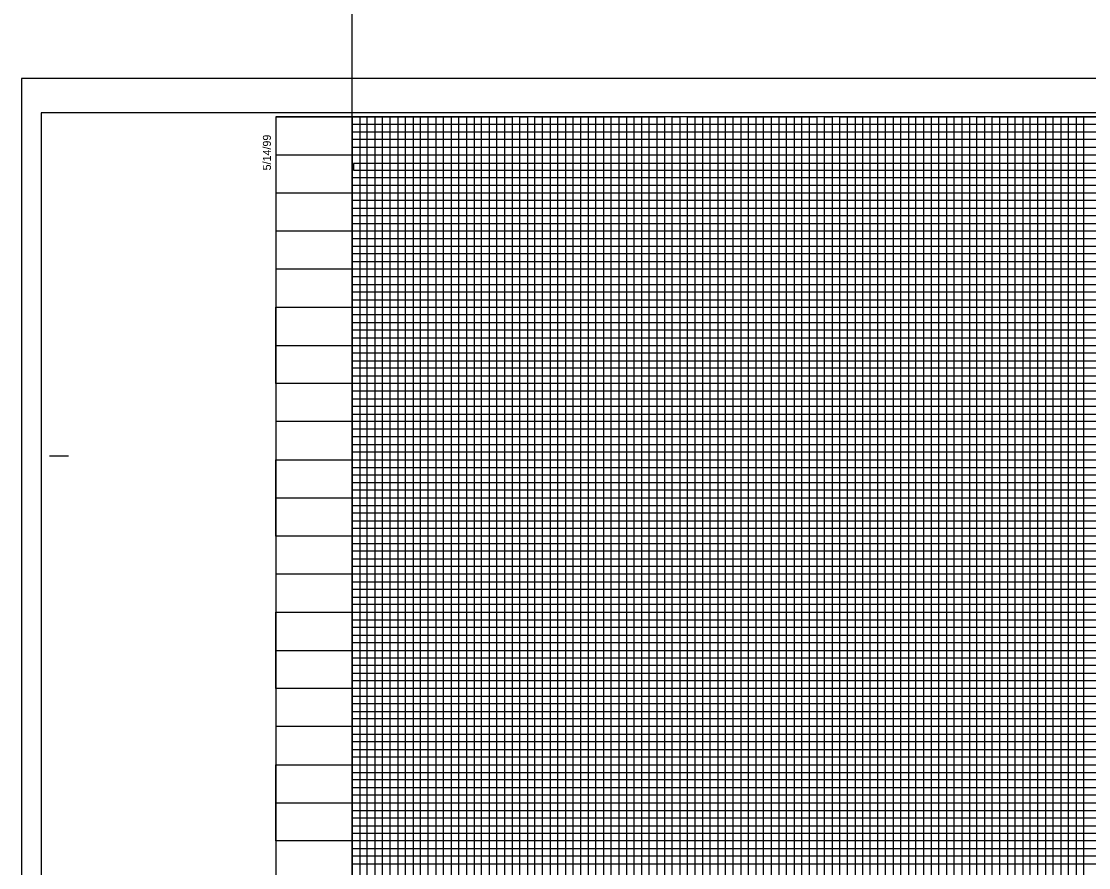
# Model space of a CAD drawing. Extents: x 2345490 to 2436403, y 465165 to 573888.
# Drawn here: x 2381550 to 2382250, y 541557 to 542112 of the extents above; entities that cross this region are included whole.
import ezdxf

# ---------------------------------------------------------------- set-up
doc = ezdxf.new("R2010")
doc.units = 0
for name, color, linetype in [('Old_Level_18', 7, 'Continuous'), ('Old_Level_41', 7, 'Continuous'), ('Old_Level_42', 7, 'Continuous'), ('Old_Level_43', 7, 'Continuous'), ('Old_Level_50', 7, 'Continuous'), ('Old_Level_51', 7, 'Continuous'), ('Old_Level_63', 7, 'Continuous')]:
    doc.layers.add(name, color=color, linetype=linetype)

msp = doc.modelspace()

# ---------------------------------------------------------------- linework, layer by layer
at = {"layer": 'Old_Level_18'}
msp.add_lwpolyline([(2383216.79875, 542049.5045), (2381716.79875, 542049.5045), (2381716.79875, 540999.5045), (2383216.79875, 540999.5045)], close=True, dxfattribs=at)
at = {"layer": 'Old_Level_41'}
msp.add_line((2381568.29875, 541827.0045), (2381580.79875, 541827.0045), dxfattribs=at)
for points in [[(2381716.79875, 542049.5045), (2381766.79875, 542049.5045), (2381766.79875, 541024.5045), (2381816.79875, 541024.5045), (2381816.79875, 542049.5045), (2381866.79875, 542049.5045), (2381866.79875, 541024.5045), (2381916.79875, 541024.5045), (2381916.79875, 542049.5045), (2381966.79875, 542049.5045), (2381966.79875, 541024.5045), (2382016.79875, 541024.5045), (2382016.79875, 542049.5045), (2382066.79875, 542049.5045), (2382066.79875, 541024.5045), (2382116.79875, 541024.5045), (2382116.79875, 542049.5045), (2382166.79875, 542049.5045), (2382166.79875, 541024.5045), (2382216.79875, 541024.5045), (2382216.79875, 542049.5045), (2382266.79875, 542049.5045)], [(2381791.79875, 541024.5045), (2381791.79875, 542049.5045), (2381841.79875, 542049.5045), (2381841.79875, 541024.5045), (2381891.79875, 541024.5045), (2381891.79875, 542049.5045), (2381941.79875, 542049.5045), (2381941.79875, 541024.5045), (2381991.79875, 541024.5045), (2381991.79875, 542049.5045), (2382041.79875, 542049.5045), (2382041.79875, 541024.5045), (2382091.79875, 541024.5045), (2382091.79875, 542049.5045), (2382141.79875, 542049.5045), (2382141.79875, 541024.5045), (2382191.79875, 541024.5045), (2382191.79875, 542049.5045), (2382241.79875, 542049.5045), (2382241.79875, 541024.5045), (2382291.79875, 541024.5045)], [(2381716.79875, 541999.5045), (2383016.74875, 541999.5045)], [(2383016.74875, 541949.5045), (2381716.79875, 541949.5045), (2381716.79875, 541899.4545), (2383216.79875, 541899.4545)], [(2383216.79875, 541874.5045), (2381716.79875, 541874.5045), (2381716.79875, 541924.5045), (2383016.74875, 541924.5045)], [(2383216.79875, 541849.5045), (2381716.79875, 541849.5045), (2381716.79875, 541799.5045), (2383216.79875, 541799.5045)], [(2383216.79875, 541774.5045), (2381716.79875, 541774.5045), (2381716.79875, 541824.5045), (2383216.79875, 541824.5045)], [(2383216.79875, 541749.5045), (2381716.79875, 541749.5045), (2381716.79875, 541699.5045), (2383216.79875, 541699.5045)], [(2383216.79875, 541649.5045), (2381716.79875, 541649.5045), (2381716.79875, 541599.5045), (2383216.79875, 541599.5045)]]:
    msp.add_lwpolyline(points, dxfattribs=at)
at = {"layer": 'Old_Level_42'}
for points in [[(2383016.74875, 541974.5045), (2381716.89875, 541974.5045), (2381716.89875, 542024.4545), (2383016.74875, 542024.4545)], [(2383216.79875, 541674.5045), (2381716.79875, 541674.5045), (2381716.79875, 541724.5045), (2383216.79875, 541724.5045)], [(2383216.79875, 541574.5045), (2381716.79875, 541574.5045), (2381716.79875, 541624.5045), (2383216.79875, 541624.5045)]]:
    msp.add_lwpolyline(points, dxfattribs=at)
at = {"layer": 'Old_Level_43'}
for p, q in [((2383166.79875, 541869.5045), (2381766.79875, 541869.5045)), ((2381766.79875, 541869.5045), (2381766.79875, 541864.5045)), ((2381766.79875, 541864.5045), (2383166.79875, 541864.5045)), ((2383166.79875, 541844.5045), (2381766.79875, 541844.5045))]:
    msp.add_line(p, q, dxfattribs=at)
for points in [[(2381771.79875, 542049.5045), (2381776.79875, 542049.5045), (2381781.79875, 542049.5045), (2381786.79875, 542049.5045), (2381796.79875, 542049.5045), (2381763.74875, 542049.5045), (2381768.74875, 542049.5045), (2381726.79875, 542049.5045), (2381731.79875, 542049.5045), (2381736.79875, 542049.5045), (2381746.79875, 542049.5045), (2381751.79875, 542049.5045), (2381756.79875, 542049.5045), (2381761.79875, 542049.5045), (2381771.79875, 542049.5045), (2381771.79875, 541024.5045)], [(2381776.79875, 541024.5045), (2381776.79875, 542049.5045), (2381781.79875, 542049.5045), (2381781.79875, 541024.5045)], [(2381786.79875, 541024.5045), (2381786.79875, 542049.5045), (2381796.79875, 542049.5045), (2381796.79875, 541024.5045)], [(2381801.79875, 541024.5045), (2381801.79875, 542049.5045), (2381806.79875, 542049.5045), (2381806.79875, 541024.5045)], [(2381811.79875, 541024.5045), (2381811.79875, 542049.5045), (2381821.79875, 542049.5045), (2381821.79875, 541024.5045)], [(2381826.79875, 541024.5045), (2381826.79875, 542049.5045), (2381831.79875, 542049.5045), (2381831.79875, 541024.5045)], [(2381836.79875, 541024.5045), (2381836.79875, 542049.5045), (2381846.79875, 542049.5045), (2381846.79875, 541024.5045)], [(2381851.79875, 541024.5045), (2381851.79875, 542049.5045), (2381856.79875, 542049.5045), (2381856.79875, 541024.5045)], [(2381861.79875, 541024.5045), (2381861.79875, 542049.5045), (2381871.79875, 542049.5045), (2381871.79875, 541024.5045)], [(2381876.79875, 541024.5045), (2381876.79875, 542049.5045), (2381881.79875, 542049.5045), (2381881.79875, 541024.5045)], [(2381886.79875, 541024.5045), (2381886.79875, 542049.5045), (2381896.79875, 542049.5045), (2381896.79875, 541024.5045)], [(2381901.79875, 541024.5045), (2381901.79875, 542049.5045), (2381906.79875, 542049.5045), (2381906.79875, 541024.5045)], [(2381911.79875, 541024.5045), (2381911.79875, 542049.5045), (2381921.79875, 542049.5045), (2381921.79875, 541024.5045)], [(2381926.79875, 541024.5045), (2381926.79875, 542049.5045), (2381931.79875, 542049.5045), (2381931.79875, 541024.5045)], [(2381936.79875, 541024.5045), (2381936.79875, 542049.5045), (2381946.79875, 542049.5045), (2381946.79875, 541024.5045)], [(2381951.79875, 541024.5045), (2381951.79875, 542049.5045), (2381956.79875, 542049.5045), (2381956.79875, 541024.5045)], [(2381961.79875, 541024.5045), (2381961.79875, 542049.5045), (2381971.79875, 542049.5045), (2381971.79875, 541024.5045)], [(2381976.79875, 541024.5045), (2381976.79875, 542049.5045), (2381976.79875, 542049.5045), (2381981.79875, 542049.5045), (2381981.79875, 541024.5045)], [(2381986.79875, 541024.5045), (2381986.79875, 542049.5045), (2381996.79875, 542049.5045), (2381996.79875, 541024.5045)], [(2382001.79875, 541024.5045), (2382001.79875, 542049.5045), (2382006.79875, 542049.5045), (2382006.79875, 541024.5045)], [(2382011.79875, 541024.5045), (2382011.79875, 542049.5045), (2382021.79875, 542049.5045), (2382021.79875, 541024.5045)], [(2382026.79875, 541024.5045), (2382026.79875, 542049.5045), (2382031.79875, 542049.5045), (2382031.79875, 541024.5045)], [(2382036.79875, 541024.5045), (2382036.79875, 542049.5045), (2382046.79875, 542049.5045), (2382046.79875, 541024.5045)], [(2382051.79875, 541024.5045), (2382051.79875, 542049.5045), (2382056.79875, 542049.5045), (2382056.79875, 541024.5045)], [(2382061.79875, 541024.5045), (2382061.79875, 542049.5045), (2382071.79875, 542049.5045), (2382071.79875, 541024.5045)], [(2382076.79875, 541024.5045), (2382076.79875, 542049.5045), (2382081.79875, 542049.5045), (2382081.79875, 541024.5045)], [(2382086.79875, 541024.5045), (2382086.79875, 542049.5045), (2382096.79875, 542049.5045), (2382096.79875, 541024.5045)], [(2382101.79875, 542049.5045), (2382101.79875, 541024.5045), (2382106.79875, 541024.5045), (2382106.79875, 542049.5045)], [(2382101.79875, 542048.9045), (2382101.79875, 541024.5045), (2382106.79875, 541024.5045), (2382106.79875, 542048.9045)], [(2382111.79875, 541024.5045), (2382111.79875, 542049.5045), (2382121.79875, 542049.5045), (2382121.79875, 541024.5045)], [(2382126.79875, 541024.5045), (2382126.79875, 542049.5045), (2382131.79875, 542049.5045), (2382131.79875, 541024.5045)], [(2382136.79875, 541024.5045), (2382136.79875, 542049.5045), (2382146.79875, 542049.5045), (2382146.79875, 541024.5045)], [(2382151.79875, 541024.5045), (2382151.79875, 542049.5045), (2382156.79875, 542049.5045), (2382156.79875, 541024.5045)], [(2382161.79875, 541024.5045), (2382161.79875, 542049.5045), (2382171.79875, 542049.5045), (2382171.79875, 541024.5045)], [(2382176.79875, 541024.5045), (2382176.79875, 542049.5045), (2382181.79875, 542049.5045), (2382181.79875, 541024.5045)], [(2382186.79875, 541024.5045), (2382186.79875, 542049.5045), (2382196.79875, 542049.5045), (2382196.79875, 541024.5045)], [(2382201.79875, 541024.5045), (2382201.79875, 542049.5045), (2382206.79875, 542049.5045), (2382206.79875, 541024.5045)], [(2382211.79875, 541024.5045), (2382211.79875, 542049.5045), (2382221.79875, 542049.5045), (2382221.79875, 541024.5045)], [(2382226.79875, 541024.5045), (2382226.79875, 542049.5045), (2382231.79875, 542049.5045), (2382231.79875, 541024.5045)], [(2382236.79875, 541024.5045), (2382236.79875, 542049.5045), (2382246.79875, 542049.5045), (2382246.79875, 541024.5045)], [(2383016.74875, 542044.5045), (2381766.79875, 542044.5045), (2381766.79875, 542039.5045), (2383016.74875, 542039.5045)], [(2383016.74875, 542034.5045), (2381766.79875, 542034.5045), (2381766.79875, 542029.5045), (2383016.74875, 542029.5045)], [(2383016.74875, 542018.7545), (2381767.79875, 542018.7545), (2381767.79875, 542014.5045), (2383016.74875, 542014.5045)], [(2383016.74875, 542009.5045), (2381766.79875, 542009.5045), (2381766.79875, 542004.5045), (2383016.74875, 542004.5045)], [(2383016.74875, 541994.5045), (2381766.79875, 541994.5045), (2381766.79875, 541989.5045), (2383016.74875, 541989.5045)], [(2383016.74875, 541984.5045), (2381766.79875, 541984.5045), (2381766.79875, 541979.5045), (2383016.74875, 541979.5045)], [(2383016.74875, 541969.5045), (2381766.79875, 541969.5045), (2381766.79875, 541964.5045), (2383016.74875, 541964.5045)], [(2383016.74875, 541959.5045), (2381766.79875, 541959.5045), (2381766.79875, 541954.5045), (2383016.74875, 541954.5045)], [(2383016.74875, 541944.5045), (2381766.79875, 541944.5045), (2381766.79875, 541939.5045), (2383016.74875, 541939.5045)], [(2383016.74875, 541934.5045), (2381766.79875, 541934.5045), (2381766.79875, 541929.5045), (2383016.74875, 541929.5045)], [(2383016.74875, 541919.5045), (2381766.79875, 541919.5045), (2381766.79875, 541914.5045), (2383016.74875, 541914.5045)], [(2383166.79875, 541909.5045), (2381766.79875, 541909.5045), (2381766.79875, 541909.5045), (2381766.79875, 541889.5045), (2383166.79875, 541889.5045)], [(2381766.79875, 541904.5045), (2383166.79875, 541904.5045)], [(2383166.79875, 541894.5045), (2381766.79875, 541894.5045)], [(2383166.79875, 541884.5045), (2381766.79875, 541884.5045), (2381766.79875, 541879.5045), (2383166.79875, 541879.5045)], [(2383166.79875, 541859.5045), (2381766.79875, 541859.5045), (2381766.79875, 541854.5045), (2383166.79875, 541854.5045)], [(2383166.79875, 541839.5045), (2381766.79875, 541839.5045), (2381766.79875, 541834.5045), (2383166.79875, 541834.5045)], [(2383166.79875, 541829.5045), (2381766.79875, 541829.5045)], [(2381766.79875, 541819.5045), (2383166.79875, 541819.5045)], [(2383166.79875, 541814.5045), (2381766.79875, 541814.5045), (2381766.79875, 541809.5045), (2383166.79875, 541809.5045)], [(2383166.79875, 541804.5045), (2381766.79875, 541804.5045), (2381766.79875, 541794.5045), (2383166.79875, 541794.5045)], [(2383166.79875, 541789.5045), (2381766.79875, 541789.5045), (2381766.79875, 541784.5045), (2383166.79875, 541784.5045)], [(2383166.79875, 541779.5045), (2381766.79875, 541779.5045), (2381766.79875, 541769.5045), (2383166.79875, 541769.5045)], [(2383166.79875, 541764.5045), (2381766.79875, 541764.5045), (2381766.79875, 541759.5045), (2383166.79875, 541759.5045)], [(2383166.79875, 541754.5045), (2381766.79875, 541754.5045), (2381766.79875, 541744.5045), (2383166.79875, 541744.5045)], [(2383166.79875, 541739.5045), (2381766.79875, 541739.5045), (2381766.79875, 541734.5045), (2383166.79875, 541734.5045)], [(2383166.79875, 541729.5045), (2381766.79875, 541729.5045), (2381766.79875, 541719.5045), (2383166.79875, 541719.5045)], [(2383166.79875, 541714.5045), (2381766.79875, 541714.5045), (2381766.79875, 541709.5045), (2383166.79875, 541709.5045)], [(2383166.79875, 541704.5045), (2381766.79875, 541704.5045), (2381766.79875, 541694.5045), (2383166.79875, 541694.5045)], [(2383166.79875, 541689.5045), (2381766.79875, 541689.5045), (2381766.79875, 541684.5045), (2383166.79875, 541684.5045)], [(2383166.79875, 541679.5045), (2381766.79875, 541679.5045), (2381766.79875, 541669.5045), (2383166.79875, 541669.5045)], [(2383166.79875, 541664.5045), (2381766.79875, 541664.5045), (2381766.79875, 541659.5045), (2383166.79875, 541659.5045)], [(2383166.79875, 541654.5045), (2381766.79875, 541654.5045), (2381766.79875, 541644.5045), (2383166.79875, 541644.5045)], [(2383166.79875, 541639.5045), (2381766.79875, 541639.5045), (2381766.79875, 541634.5045), (2383166.79875, 541634.5045)], [(2383166.79875, 541629.5045), (2381766.79875, 541629.5045), (2381766.79875, 541619.5045), (2383166.79875, 541619.5045)], [(2383166.79875, 541614.5045), (2381766.79875, 541614.5045), (2381766.79875, 541609.5045), (2383166.79875, 541609.5045)], [(2383166.79875, 541604.5045), (2381766.79875, 541604.5045), (2381766.79875, 541594.5045), (2383166.79875, 541594.5045)], [(2383166.79875, 541589.5045), (2381766.79875, 541589.5045), (2381766.79875, 541584.5045), (2383166.79875, 541584.5045)], [(2383166.79875, 541579.5045), (2381766.79875, 541579.5045), (2381766.79875, 541569.5045), (2383166.79875, 541569.5045)], [(2383166.79875, 541564.5045), (2381766.79875, 541564.5045), (2381766.79875, 541559.5045), (2383166.79875, 541559.5045)]]:
    msp.add_lwpolyline(points, dxfattribs=at)
at = {"layer": 'Old_Level_50'}
msp.add_lwpolyline([(2383229.29875, 542052.0545), (2381562.79875, 542052.0545), (2381562.79875, 540996.9545), (2383229.29875, 540996.9545)], close=True, dxfattribs=at)
at = {"layer": 'Old_Level_51'}
msp.add_lwpolyline([(2383233.79875, 542074.5045), (2381549.79875, 542074.5045), (2381549.79875, 540974.5045), (2383233.79875, 540974.5045)], close=True, dxfattribs=at)
at = {"layer": 'Old_Level_63'}
msp.add_line((2381766.79875, 541024.5045), (2381766.79875, 543524.5045), dxfattribs=at)

# ---------------------------------------------------------------- texts
at = {"layer": 'Old_Level_41'}
msp.add_text('5/14/99', height=5.25, rotation=90, dxfattribs=at).set_placement((2381713.54875, 542014.3045))

doc.saveas('drawing.dxf')
